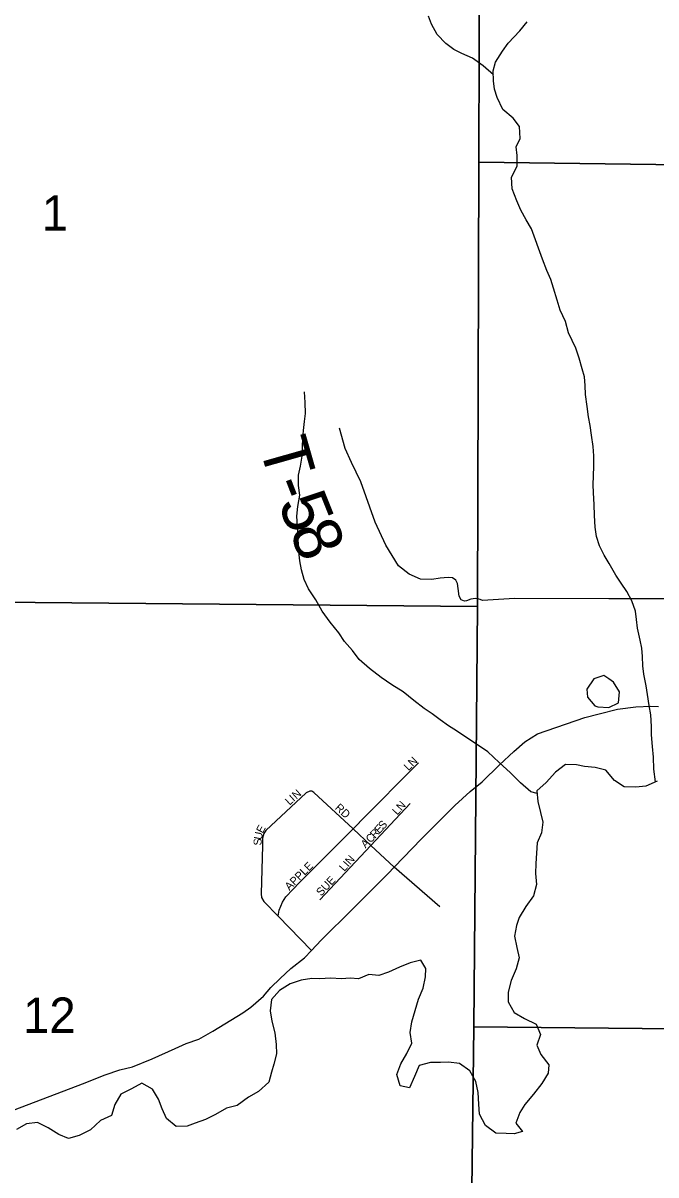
# Model space of a CAD drawing. Extents: x 2043100 to 2470832, y 443715 to 810583.
# Drawn here: x 2288517 to 2292469, y 693056 to 700252 of the extents above; entities that cross this region are included whole.
import ezdxf

# ---------------------------------------------------------------- set-up
doc = ezdxf.new("R2010")
doc.units = 0
for name, color, linetype in [('GM_X_Major_Lake', 7, 'Continuous'), ('GM_X_Minor_Lake', 7, 'Continuous'), ('GM_X_Minor_River', 7, 'Continuous'), ('GM_X_Section', 7, 'Continuous'), ('GM_X_Section_Text', 7, 'Continuous'), ('GM_X_State_Route', 7, 'Continuous'), ('GM_X_Township_Road', 7, 'Continuous'), ('GM_X_Township_Road_Text', 7, 'Continuous'), ('GM_X_Township_Subdivision', 7, 'Continuous'), ('GM_X_Township_Subdivision_Text', 7, 'Continuous')]:
    doc.layers.add(name, color=color, linetype=linetype)

msp = doc.modelspace()

# ---------------------------------------------------------------- linework, layer by layer
at = {"layer": 'GM_X_Major_Lake'}
for points in [[(2292477.1, 695516.5), (2292407, 695484.3), (2292343, 695478.2), (2292270.9, 695480.1), (2292210.8, 695520), (2292156.7, 695584.1), (2292090.6, 695602), (2292022.5, 695607.9), (2291972.4, 695617.9), (2291904.3, 695619.8), (2291842.3, 695571.6), (2291784.3, 695507.4), (2291726.2, 695455.2), (2291732.3, 695389.1), (2291748.3, 695320.9), (2291762.4, 695258.8), (2291754.4, 695192.7), (2291726.4, 695130.5), (2291718.5, 695002.3), (2291716.5, 694938.2), (2291722.5, 694870), (2291704.6, 694799.8), (2291656.5, 694733.7), (2291614.5, 694663.4), (2291598.5, 694613.3)], [(2291598.5, 694613.3), (2291586.6, 694547.2), (2291600.6, 694477.1), (2291614.7, 694413), (2291596.7, 694342.8), (2291564.7, 694270.6), (2291546.7, 694198.4), (2291546.7, 694138.3), (2291582.8, 694070.2), (2291648.9, 694032.3), (2291721, 693998.3), (2291749.1, 693932.2), (2291725.1, 693866), (2291751.2, 693808), (2291799.3, 693743.9), (2291795.3, 693691.8), (2291757.3, 693627.6), (2291705.2, 693561.4), (2291651.2, 693495.2), (2291619.2, 693445.1), (2291593.2, 693378.9), (2291635.3, 693326.9), (2291583.2, 693312.7), (2291533.2, 693314.7), (2291469.1, 693316.6), (2291405, 693364.6), (2291366.9, 693434.7), (2291362.9, 693498.8), (2291358.8, 693570.9), (2291344.8, 693639), (2291306.7, 693707.1), (2291242.6, 693751.1), (2291174.5, 693761), (2291124.4, 693758.9), (2291060.3, 693758.8), (2290990.3, 693738.7), (2290962.3, 693670.5), (2290930.3, 693600.3), (2290872.2, 693612.2), (2290850.1, 693682.4), (2290876.1, 693750.5), (2290914.1, 693814.7), (2290944.1, 693878.9), (2290934.1, 693945), (2290944.1, 694013.2), (2290966, 694083.3), (2290986, 694153.5), (2291016, 694223.7), (2291030, 694293.8), (2291032, 694345.9), (2291001.9, 694398), (2290933.8, 694379.9), (2290867.8, 694353.7), (2290799.7, 694323.5), (2290739.6, 694301.4), (2290675.6, 694307.3), (2290611.5, 694281.2), (2290559.4, 694285.1), (2290505.4, 694281), (2290437.3, 694284.9), (2290371.2, 694280.8), (2290321.1, 694282.7), (2290253.1, 694272.6), (2290185, 694250.5), (2290118.9, 694208.3), (2290068.9, 694152.1), (2290060.9, 694081.9), (2290071, 694015.8), (2290089, 693943.7), (2290097.1, 693871.6), (2290099.1, 693811.5), (2290083.1, 693747.3), (2290069.1, 693697.2), (2290051.2, 693635.1), (2289987.1, 693576.8), (2289925.1, 693542.7), (2289853, 693490.5), (2289786.9, 693472.3), (2289718.9, 693434.2), (2289656.8, 693402), (2289590.7, 693379.9), (2289540.7, 693359.7), (2289472.6, 693357.6), (2289412.5, 693407.6), (2289386.4, 693469.7), (2289362.4, 693529.8), (2289324.3, 693591.9), (2289258.2, 693629.8), (2289194.1, 693593.7), (2289128.1, 693559.5), (2289090, 693495.3), (2289068.1, 693427.2), (2289000, 693397), (2288937.9, 693336.8), (2288867.9, 693302.6), (2288799.8, 693284.5), (2288739.7, 693308.4), (2288673.6, 693350.4), (2288607.5, 693384.4), (2288537.4, 693374.2), (2288475.4, 693340.1)]]:
    msp.add_lwpolyline(points, dxfattribs=at)
at = {"layer": 'GM_X_Minor_Lake'}
for points in [[(2292174.2, 696154.4), (2292142.8, 696175.5), (2292080.7, 696155.3), (2292036.8, 696091), (2292040.9, 696040.9), (2292087.1, 695986.9)], [(2292087.1, 695986.9), (2292107.1, 695981), (2292175.3, 695975.2), (2292235.3, 696005.4), (2292241.2, 696073.6), (2292205, 696133.6), (2292174.2, 696154.4)]]:
    msp.add_lwpolyline(points, dxfattribs=at)
at = {"layer": 'GM_X_Minor_River'}
for points in [[(2291454, 699927.7), (2291391, 699983.6), (2291322.7, 700031.5), (2291256.5, 700061.3), (2291206.4, 700087.2), (2291156.2, 700123.2), (2291102, 700181.1), (2291067.8, 700245.1), (2291049.7, 700295.2)], [(2292466.6, 695511.6), (2292456.6, 695591.2), (2292454.5, 695665.4), (2292448.3, 695731.5), (2292442.1, 695805.7), (2292442, 695857.8), (2292437.8, 695929.9), (2292427.7, 695988), (2292417.5, 696058.1), (2292407.4, 696112.2), (2292393.2, 696184.3), (2292387.1, 696236.4), (2292384.9, 696294.5), (2292380.8, 696346.6), (2292370.7, 696396.7), (2292354.5, 696470.8), (2292348.4, 696524.9), (2292342.2, 696577), (2292318.1, 696643.1), (2292287.9, 696701.1), (2292251.7, 696753.1), (2292219.5, 696803.1), (2292177.3, 696875.1), (2292145.1, 696927.2), (2292116.9, 696985.2), (2292098.8, 697045.3), (2292090.6, 697103.4), (2292084.5, 697175.5), (2292084.3, 697243.6), (2292080.1, 697317.8), (2292078, 697369.9), (2292079.9, 697422), (2292081.8, 697486.2), (2292081.6, 697548.3), (2292077.5, 697606.4), (2292067.3, 697676.5), (2292059.2, 697738.7), (2292047, 697792.7), (2292038.9, 697856.9), (2292028.7, 697931), (2292026.6, 697987.1), (2292022.4, 698041.2), (2292008.3, 698091.3), (2291990.1, 698157.4), (2291969.9, 698221.4), (2291923.6, 698317.5), (2291903.4, 698387.6), (2291871.2, 698457.7), (2291853.1, 698519.7), (2291828.9, 698595.8), (2291812.7, 698649.9), (2291788.5, 698705.9), (2291760.3, 698776), (2291736.1, 698846.1), (2291716, 698898.2), (2291691.8, 698966.2), (2291659.6, 699022.2), (2291625.4, 699082.3), (2291601.2, 699142.3), (2291571, 699216.4), (2291566.8, 699288.5), (2291602.7, 699358.8), (2291602.6, 699425), (2291596.5, 699479.1), (2291620.4, 699531.3), (2291616.2, 699605.4), (2291578, 699657.4), (2291513.8, 699711.3), (2291477.6, 699787.4), (2291461.4, 699839.5), (2291455.3, 699891.6), (2291453.1, 699953.7), (2291467, 700007.9), (2291510.9, 700076.2), (2291546.9, 700126.4), (2291618.9, 700202.8), (2291664.8, 700259.1)], [(2291727.7, 695438.9), (2291687.6, 695448.5), (2291623.4, 695504.4), (2291561.1, 695568.3), (2291490.9, 695632.2), (2291418.6, 695698.1), (2291336.3, 695756), (2291282.1, 695789.9), (2291223.9, 695829.8), (2291173.8, 695861.7), (2291121.6, 695899.6), (2291071.5, 695937.5), (2291021.3, 695969.4), (2290957.1, 696019.3), (2290890.8, 696073.2), (2290820.6, 696117.1), (2290752.4, 696163), (2290680.1, 696218.9), (2290615.9, 696276.8), (2290573.7, 696332.8), (2290523.5, 696388.8), (2290489.3, 696442.8), (2290435.1, 696508.7), (2290384.8, 696578.7), (2290344.6, 696648.7), (2290300.4, 696716.8), (2290272.2, 696774.8), (2290256, 696836.9), (2290245.9, 696892.9), (2290239.8, 696949), (2290235.6, 697029.2), (2290231.4, 697107.4), (2290227.2, 697171.5), (2290233.1, 697231.7), (2290245, 697301.8), (2290236.8, 697361.9), (2290236.7, 697428.1), (2290248.6, 697484.2), (2290260.5, 697546.4), (2290262.3, 697606.6), (2290264.2, 697656.7), (2290268.1, 697706.8), (2290274, 697762.9), (2290279.9, 697813.1), (2290277.8, 697881.2), (2290273.6, 697947.4)]]:
    msp.add_lwpolyline(points, dxfattribs=at)
at = {"layer": 'GM_X_Section'}
for points in [[(2291388.9, 704755.7), (2296369.9, 704701.1), (2296254.6, 699319.1), (2291363.5, 699382.8), (2291370.4, 701595.9)], [(2291370.4, 701595.9), (2291363.5, 699382.8), (2291354, 696607.4), (2286056.9, 696655.8), (2286065, 701670.2)], [(2296254.6, 699319.1), (2296167.4, 693933.5), (2291332.5, 693981.9), (2291354, 696607.4), (2291363.5, 699382.8)], [(2286056.9, 696655.8), (2291354, 696607.4), (2291332.5, 693981.9), (2291298.1, 691272.2), (2286029, 691327)], [(2291332.5, 693981.9), (2296167.4, 693933.5), (2296074.7, 688501.8), (2291263.2, 688598.5), (2291298.1, 691272.2)]]:
    msp.add_lwpolyline(points, close=True, dxfattribs=at)
at = {"layer": 'GM_X_State_Route'}
msp.add_lwpolyline([(2288467.9, 693465.7), (2288887.8, 693625.3), (2289029.8, 693681.8), (2289121.8, 693712.1), (2289199.8, 693730.4), (2289323.8, 693780.8), (2289465.8, 693845.4), (2289535.8, 693877.6), (2289613.8, 693903.9), (2289701.7, 693954.3), (2289889.6, 694069), (2289939.5, 694103.2), (2290017.4, 694173.6), (2290063.3, 694225.9), (2290123.2, 694284.1), (2290189.1, 694344.5), (2290275, 694412.8), (2290317.8, 694458.4), (2290378.8, 694523.4), (2290576.4, 694718.3), (2290796, 694939.4), (2290834.6, 694979.4), (2291005.6, 695156.5), (2291213.3, 695363.5), (2291309.1, 695452), (2291383, 695512.3), (2291492.8, 695618.8), (2291580.7, 695701.3), (2291650.6, 695761.6), (2291728.5, 695811.9), (2292024.5, 695913), (2292114.5, 695937.3), (2292228.6, 695965.7), (2292344.6, 695980), (2292436.8, 695983.7), (2292484.7, 695982.5)], dxfattribs=at)
at = {"layer": 'GM_X_Township_Road'}
for points in [[(2292695.1, 696654.5), (2292174.6, 696655), (2291586.1, 696657.3), (2291385.9, 696644.7), (2291371.9, 696650.7), (2291357.9, 696654.7), (2291341.9, 696656.6), (2291313.8, 696652.5), (2291285.8, 696642.5), (2291273.8, 696640.4), (2291253.8, 696648.4), (2291239.7, 696672.4), (2291233.6, 696718.5), (2291229.5, 696750.5), (2291219.4, 696770.5), (2291199.4, 696786.5), (2291171.3, 696788.4), (2291121.3, 696784.3), (2291069.3, 696776.1), (2290999.2, 696777.9), (2290927.1, 696809.8), (2290860.9, 696861.7), (2290782.4, 696989.8), (2290716, 697133.9), (2290625.2, 697386.2), (2290568.8, 697506.3), (2290528.5, 697594.4), (2290492.2, 697720.5)], [(2291120.1, 694731), (2290834.6, 694979.4)]]:
    msp.add_lwpolyline(points, dxfattribs=at)
at = {"layer": 'GM_X_Township_Subdivision'}
for points in [[(2290617.4, 695258.6), (2290617.9, 695259.1), (2290986.1, 695629.4)], [(2290834.6, 694979.4), (2290688.9, 695114.8), (2290577.5, 695218.4), (2290332.7, 695445.8), (2290320.7, 695453.9), (2290308.7, 695453.9), (2290284.7, 695442), (2290033.4, 695208.6), (2290021.3, 695188.6), (2290013.1, 695160.6), (2290012.9, 695114.5), (2290003.5, 694812), (2290005.4, 694789.9), (2290021.3, 694763.8), (2290109.1, 694673.4), (2290317.8, 694458.4)], [(2290369.6, 694774.3), (2290688.9, 695114.8), (2290934.9, 695377.1)], [(2290109.1, 694673.4), (2290117.1, 694709.3), (2290137.4, 694759.3), (2290157.6, 694793.3), (2290246.1, 694885.1), (2290577.5, 695218.4), (2290617.4, 695258.6)]]:
    msp.add_lwpolyline(points, dxfattribs=at)

# ---------------------------------------------------------------- texts
at = {"layer": 'GM_X_Section_Text'}
for s, height, p in [('1', 220.8, (2288633.4, 698955.4)), ('12', 220.83, (2288516.8, 693943.3))]:
    msp.add_text(s, height=height, rotation=0.00001, dxfattribs=at).set_placement(p)
at = {"layer": 'GM_X_Township_Road_Text'}
for s, rotation, p in [('T', 285.91891, (2289989.4, 697615)), ('-', 291.15911, (2290060.4, 697370.8)), ('5', 291.80714, (2290106.3, 697252.5)), ('8', 292.58188, (2290176.6, 697076.8))]:
    msp.add_text(s, height=300, rotation=rotation, dxfattribs=at).set_placement(p)
at = {"layer": 'GM_X_Township_Subdivision_Text'}
for s, rotation, p in [('LN', 44.99159, (2290924, 695577.7)), ('N', 41.73297, (2290223.3, 695400.4)), ('L', 41.73336, (2290180.6, 695362.3)), ('I', 41.69161, (2290206.9, 695385.7)), ('RD', 317.1199, (2290461, 695344.7)), ('LN', 47.12768, (2290853.4, 695300.3)), ('E', 62.20073, (2290013.8, 695186.1)), ('E', 47.12247, (2290741.5, 695184.2)), ('S', 47.12538, (2290765.5, 695210)), ('U', 78.82721, (2290006.6, 695146.5)), ('C', 46.86895, (2290687.4, 695126.1)), ('R', 47.10401, (2290714.5, 695155.2)), ('S', 88.98915, (2290006.2, 695113.7)), ('A', 45.57185, (2290655.7, 695093.8)), ('APPLE', 44.99635, (2290180.4, 694829.7)), ('LIN', 48.57463, (2290523.2, 694948.1)), ('SUE', 46.5472, (2290378.2, 694794.3))]:
    msp.add_text(s, height=50, rotation=rotation, dxfattribs=at).set_placement(p)

doc.saveas('drawing.dxf')
